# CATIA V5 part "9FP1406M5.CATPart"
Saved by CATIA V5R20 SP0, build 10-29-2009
Part number: 9FP1406M5
Revision: ANY
Definition: UNKNOWN
Nomenclature: 9FP1406M5
Source: Unknown
Bounding box of the stored display mesh (mm): x -6.727 to 6.727, y 0 to 6, z -6.9 to 6.9
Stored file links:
  C:\Users\Utente\Desktop\IO LAVORO\3D X SITO CF\CUMSA\3D files PW\pw081230\pw081230_ejection\9FP1406M5.CATPart
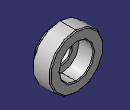
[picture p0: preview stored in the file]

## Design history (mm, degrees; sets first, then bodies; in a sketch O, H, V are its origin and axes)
Body1 "Chaflán1" (main body)
  Solid1: solid without history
